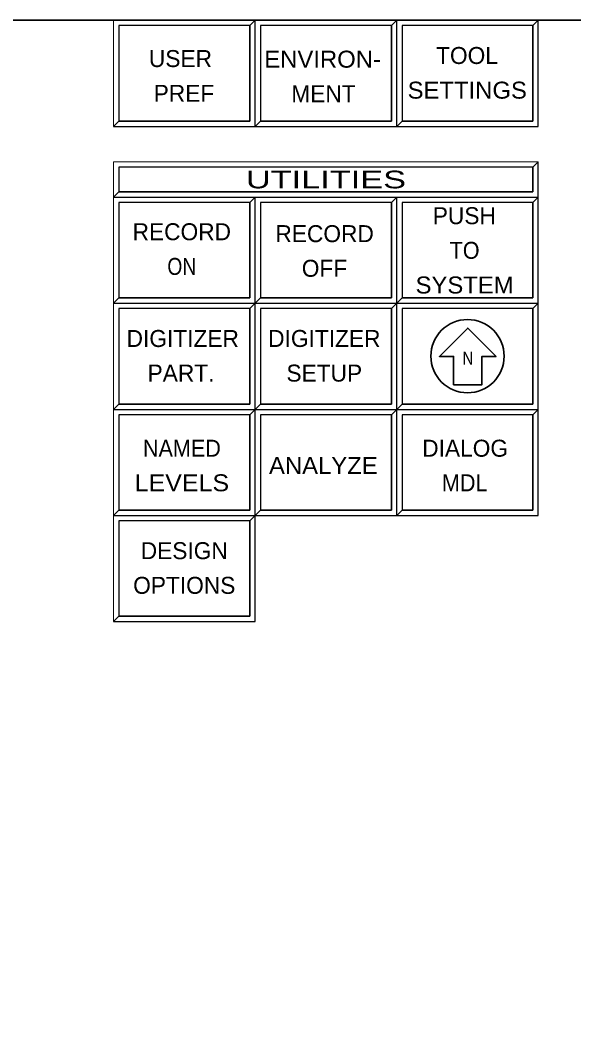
# Model space of a CAD drawing. Extents: x 95906.8 to 95923.6, y 90964.8 to 90972.8.
# Drawn here: x 95914.669 to 95916.232, y 90969.888 to 90972.762 of the extents above; entities that cross this region are included whole.
import ezdxf
from ezdxf.enums import TextEntityAlignment as Align

# ---------------------------------------------------------------- set-up
doc = ezdxf.new("R2010")
doc.units = 0
doc.header["$LTSCALE"] = 0.019
for name, color, linetype, lineweight in [('11', 7, 'Continuous', 25), ('18', 7, 'Continuous', 25), ('2', 7, 'Continuous', 13), ('3', 7, 'Continuous', 25), ('6', 7, 'Continuous', 25), ('7', 7, 'Continuous', 35)]:
    doc.layers.add(name, color=color, linetype=linetype, lineweight=lineweight)

msp = doc.modelspace()

# ---------------------------------------------------------------- linework, layer by layer
at = {"layer": '11'}
for points in [[(95914.9473, 90972.4767), (95915.3173, 90972.4767), (95915.3173, 90972.7467), (95914.9473, 90972.7467)], [(95915.3473, 90972.4767), (95915.7173, 90972.4767), (95915.7173, 90972.7467), (95915.3473, 90972.7467)], [(95915.7473, 90972.4767), (95916.1173, 90972.4767), (95916.1173, 90972.7467), (95915.7473, 90972.7467)], [(95914.9473, 90971.9767), (95915.3173, 90971.9767), (95915.3173, 90972.2467), (95914.9473, 90972.2467)], [(95915.3473, 90971.9767), (95915.7173, 90971.9767), (95915.7173, 90972.2467), (95915.3473, 90972.2467)], [(95915.7473, 90971.9767), (95916.1173, 90971.9767), (95916.1173, 90972.2467), (95915.7473, 90972.2467)], [(95914.9473, 90971.6767), (95915.3173, 90971.6767), (95915.3173, 90971.9467), (95914.9473, 90971.9467)], [(95915.3473, 90971.6767), (95915.7173, 90971.6767), (95915.7173, 90971.9467), (95915.3473, 90971.9467)], [(95915.7473, 90971.6767), (95916.1173, 90971.6767), (95916.1173, 90971.9467), (95915.7473, 90971.9467)], [(95914.9473, 90971.3767), (95915.3173, 90971.3767), (95915.3173, 90971.6467), (95914.9473, 90971.6467)], [(95915.3473, 90971.3767), (95915.7173, 90971.3767), (95915.7173, 90971.6467), (95915.3473, 90971.6467)], [(95915.7473, 90971.3767), (95916.1173, 90971.3767), (95916.1173, 90971.6467), (95915.7473, 90971.6467)], [(95914.9473, 90971.0767), (95915.3173, 90971.0767), (95915.3173, 90971.3467), (95914.9473, 90971.3467)]]:
    msp.add_lwpolyline(points, close=True, dxfattribs=at)
at = {"layer": '18'}
msp.add_lwpolyline([(95914.9473, 90972.2767), (95916.1173, 90972.2767), (95916.1173, 90972.3467), (95914.9473, 90972.3467)], close=True, dxfattribs=at)
at = {"layer": '2'}
for points in [[(95914.9323, 90972.7617), (95914.9323, 90972.4617), (95914.9473, 90972.4767), (95914.9473, 90972.7467), (95915.3173, 90972.7467), (95915.3323, 90972.7617)], [(95915.3323, 90972.7617), (95915.3323, 90972.4617), (95915.3473, 90972.4767), (95915.3473, 90972.7467), (95915.7173, 90972.7467), (95915.7323, 90972.7617)], [(95915.7323, 90972.7617), (95915.7323, 90972.4617), (95915.7473, 90972.4767), (95915.7473, 90972.7467), (95916.1173, 90972.7467), (95916.1323, 90972.7617)], [(95914.9323, 90972.3617), (95914.9323, 90972.2617), (95914.9473, 90972.2767), (95914.9473, 90972.3467), (95916.1173, 90972.3467), (95916.1323, 90972.3617)], [(95914.9323, 90972.2617), (95914.9323, 90971.9617), (95914.9473, 90971.9767), (95914.9473, 90972.2467), (95915.3173, 90972.2467), (95915.3323, 90972.2617)], [(95915.3323, 90972.2617), (95915.3323, 90971.9617), (95915.3473, 90971.9767), (95915.3473, 90972.2467), (95915.7173, 90972.2467), (95915.7323, 90972.2617)], [(95915.7323, 90972.2617), (95915.7323, 90971.9617), (95915.7473, 90971.9767), (95915.7473, 90972.2467), (95916.1173, 90972.2467), (95916.1323, 90972.2617)], [(95914.9323, 90971.9617), (95914.9323, 90971.6617), (95914.9473, 90971.6767), (95914.9473, 90971.9467), (95915.3173, 90971.9467), (95915.3323, 90971.9617)], [(95915.3323, 90971.9617), (95915.3323, 90971.6617), (95915.3473, 90971.6767), (95915.3473, 90971.9467), (95915.7173, 90971.9467), (95915.7323, 90971.9617)], [(95915.7323, 90971.9617), (95915.7323, 90971.6617), (95915.7473, 90971.6767), (95915.7473, 90971.9467), (95916.1173, 90971.9467), (95916.1323, 90971.9617)], [(95914.9323, 90971.6617), (95914.9323, 90971.3617), (95914.9473, 90971.3767), (95914.9473, 90971.6467), (95915.3173, 90971.6467), (95915.3323, 90971.6617)], [(95915.3323, 90971.6617), (95915.3323, 90971.3617), (95915.3473, 90971.3767), (95915.3473, 90971.6467), (95915.7173, 90971.6467), (95915.7323, 90971.6617)], [(95915.7323, 90971.6617), (95915.7323, 90971.3617), (95915.7473, 90971.3767), (95915.7473, 90971.6467), (95916.1173, 90971.6467), (95916.1323, 90971.6617)], [(95914.9323, 90971.3617), (95914.9323, 90971.0617), (95914.9473, 90971.0767), (95914.9473, 90971.3467), (95915.3173, 90971.3467), (95915.3323, 90971.3617)]]:
    msp.add_lwpolyline(points, close=True, dxfattribs=at)
at = {"layer": '3'}
for points in [[(95914.9323, 90972.4617), (95915.3323, 90972.4617), (95915.3323, 90972.7617), (95915.3173, 90972.7467), (95915.3173, 90972.4767), (95914.9473, 90972.4767)], [(95915.3323, 90972.4617), (95915.7323, 90972.4617), (95915.7323, 90972.7617), (95915.7173, 90972.7467), (95915.7173, 90972.4767), (95915.3473, 90972.4767)], [(95915.7323, 90972.4617), (95916.1323, 90972.4617), (95916.1323, 90972.7617), (95916.1173, 90972.7467), (95916.1173, 90972.4767), (95915.7473, 90972.4767)], [(95914.9323, 90972.2617), (95916.1323, 90972.2617), (95916.1323, 90972.3617), (95916.1173, 90972.3467), (95916.1173, 90972.2767), (95914.9473, 90972.2767)], [(95914.9323, 90971.9617), (95915.3323, 90971.9617), (95915.3323, 90972.2617), (95915.3173, 90972.2467), (95915.3173, 90971.9767), (95914.9473, 90971.9767)], [(95915.3323, 90971.9617), (95915.7323, 90971.9617), (95915.7323, 90972.2617), (95915.7173, 90972.2467), (95915.7173, 90971.9767), (95915.3473, 90971.9767)], [(95915.7323, 90971.9617), (95916.1323, 90971.9617), (95916.1323, 90972.2617), (95916.1173, 90972.2467), (95916.1173, 90971.9767), (95915.7473, 90971.9767)], [(95914.9323, 90971.6617), (95915.3323, 90971.6617), (95915.3323, 90971.9617), (95915.3173, 90971.9467), (95915.3173, 90971.6767), (95914.9473, 90971.6767)], [(95915.3323, 90971.6617), (95915.7323, 90971.6617), (95915.7323, 90971.9617), (95915.7173, 90971.9467), (95915.7173, 90971.6767), (95915.3473, 90971.6767)], [(95915.7323, 90971.6617), (95916.1323, 90971.6617), (95916.1323, 90971.9617), (95916.1173, 90971.9467), (95916.1173, 90971.6767), (95915.7473, 90971.6767)], [(95914.9323, 90971.3617), (95915.3323, 90971.3617), (95915.3323, 90971.6617), (95915.3173, 90971.6467), (95915.3173, 90971.3767), (95914.9473, 90971.3767)], [(95915.3323, 90971.3617), (95915.7323, 90971.3617), (95915.7323, 90971.6617), (95915.7173, 90971.6467), (95915.7173, 90971.3767), (95915.3473, 90971.3767)], [(95915.7323, 90971.3617), (95916.1323, 90971.3617), (95916.1323, 90971.6617), (95916.1173, 90971.6467), (95916.1173, 90971.3767), (95915.7473, 90971.3767)], [(95914.9323, 90971.0617), (95915.3323, 90971.0617), (95915.3323, 90971.3617), (95915.3173, 90971.3467), (95915.3173, 90971.0767), (95914.9473, 90971.0767)]]:
    msp.add_lwpolyline(points, close=True, dxfattribs=at)
at = {"layer": '6', "lineweight": 35}
msp.add_lwpolyline([(95915.893, 90971.7314), (95915.893, 90971.8114), (95915.853, 90971.8114), (95915.933, 90971.8914), (95916.013, 90971.8114), (95915.973, 90971.8114), (95915.973, 90971.7314)], close=True, dxfattribs=at)
msp.add_circle((95915.9323, 90971.8122), 0.1036, dxfattribs=at)
at = {"layer": '7'}
msp.add_lwpolyline([(95906.8323, 90972.7617), (95918.8323, 90972.7617), (95918.8323, 90964.7617), (95906.8323, 90964.7617)], close=True, dxfattribs=at)

# ---------------------------------------------------------------- texts
at = {"layer": '6'}
for s, p in [('USER', (95915.1211, 90972.6296)), ('TOOL', (95915.9309, 90972.6383)), ('PREF', (95915.131, 90972.5313)), ('MENT', (95915.5253, 90972.5303)), ('PUSH', (95915.9233, 90972.1854)), ('RECORD', (95915.1249, 90972.14)), ('RECORD', (95915.5285, 90972.1346)), ('OFF', (95915.5281, 90972.0366)), ('DIGITIZER', (95915.1276, 90971.8382)), ('DIGITIZER', (95915.5277, 90971.8383)), ('PART.', (95915.1227, 90971.7404)), ('SETUP', (95915.5276, 90971.7403)), ('DIALOG', (95915.9256, 90971.528)), ('DESIGN', (95915.1319, 90971.2383)), ('OPTIONS', (95915.1319, 90971.1403))]:
    msp.add_text(s, height=0.048, dxfattribs=at).set_placement(p, align=Align.CENTER)
for s, height, width, p in [('ENVIRON-', 0.048, 1.05, (95915.5228, 90972.6279)), ('SETTINGS', 0.048, 1.05, (95915.9316, 90972.5403)), ('TO', 0.048, 0.95, (95915.9241, 90972.0874)), ('ON', 0.048, 0.85, (95915.1249, 90972.042)), ('SYSTEM', 0.048, 1.05, (95915.9241, 90971.9894)), ('N', 0.0375, 0.85, (95915.9333, 90971.7879)), ('NAMED', 0.048, 0.95, (95915.1252, 90971.528)), ('ANALYZE', 0.048, 1.05, (95915.5249, 90971.4791)), ('LEVELS', 0.048, 1.1, (95915.1252, 90971.4302)), ('MDL', 0.048, 0.95, (95915.9244, 90971.4302))]:
    msp.add_text(s, height=height, dxfattribs=dict(at, width=width)).set_placement(p, align=Align.CENTER)
at = {"layer": '7', "width": 1.45}
msp.add_text('       UTILITIES       ', height=0.04999, dxfattribs=at).set_placement((95915.5323, 90972.2867), align=Align.CENTER)

doc.saveas('drawing.dxf')
